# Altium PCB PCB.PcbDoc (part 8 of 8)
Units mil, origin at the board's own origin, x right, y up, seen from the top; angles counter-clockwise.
Board outline 11229.24 x 7764.43 mil, 14 copper layers (Top Layer, GND1, Signal 1, GND2, Signal 2, GND3, Singal 3, Power 1, GND4, Power 2, GND5, Power 3, GND6, Bottom Layer), stack 91.892 mil thick; 877 components, 305 nets, 2660 pads, 2851 vias.
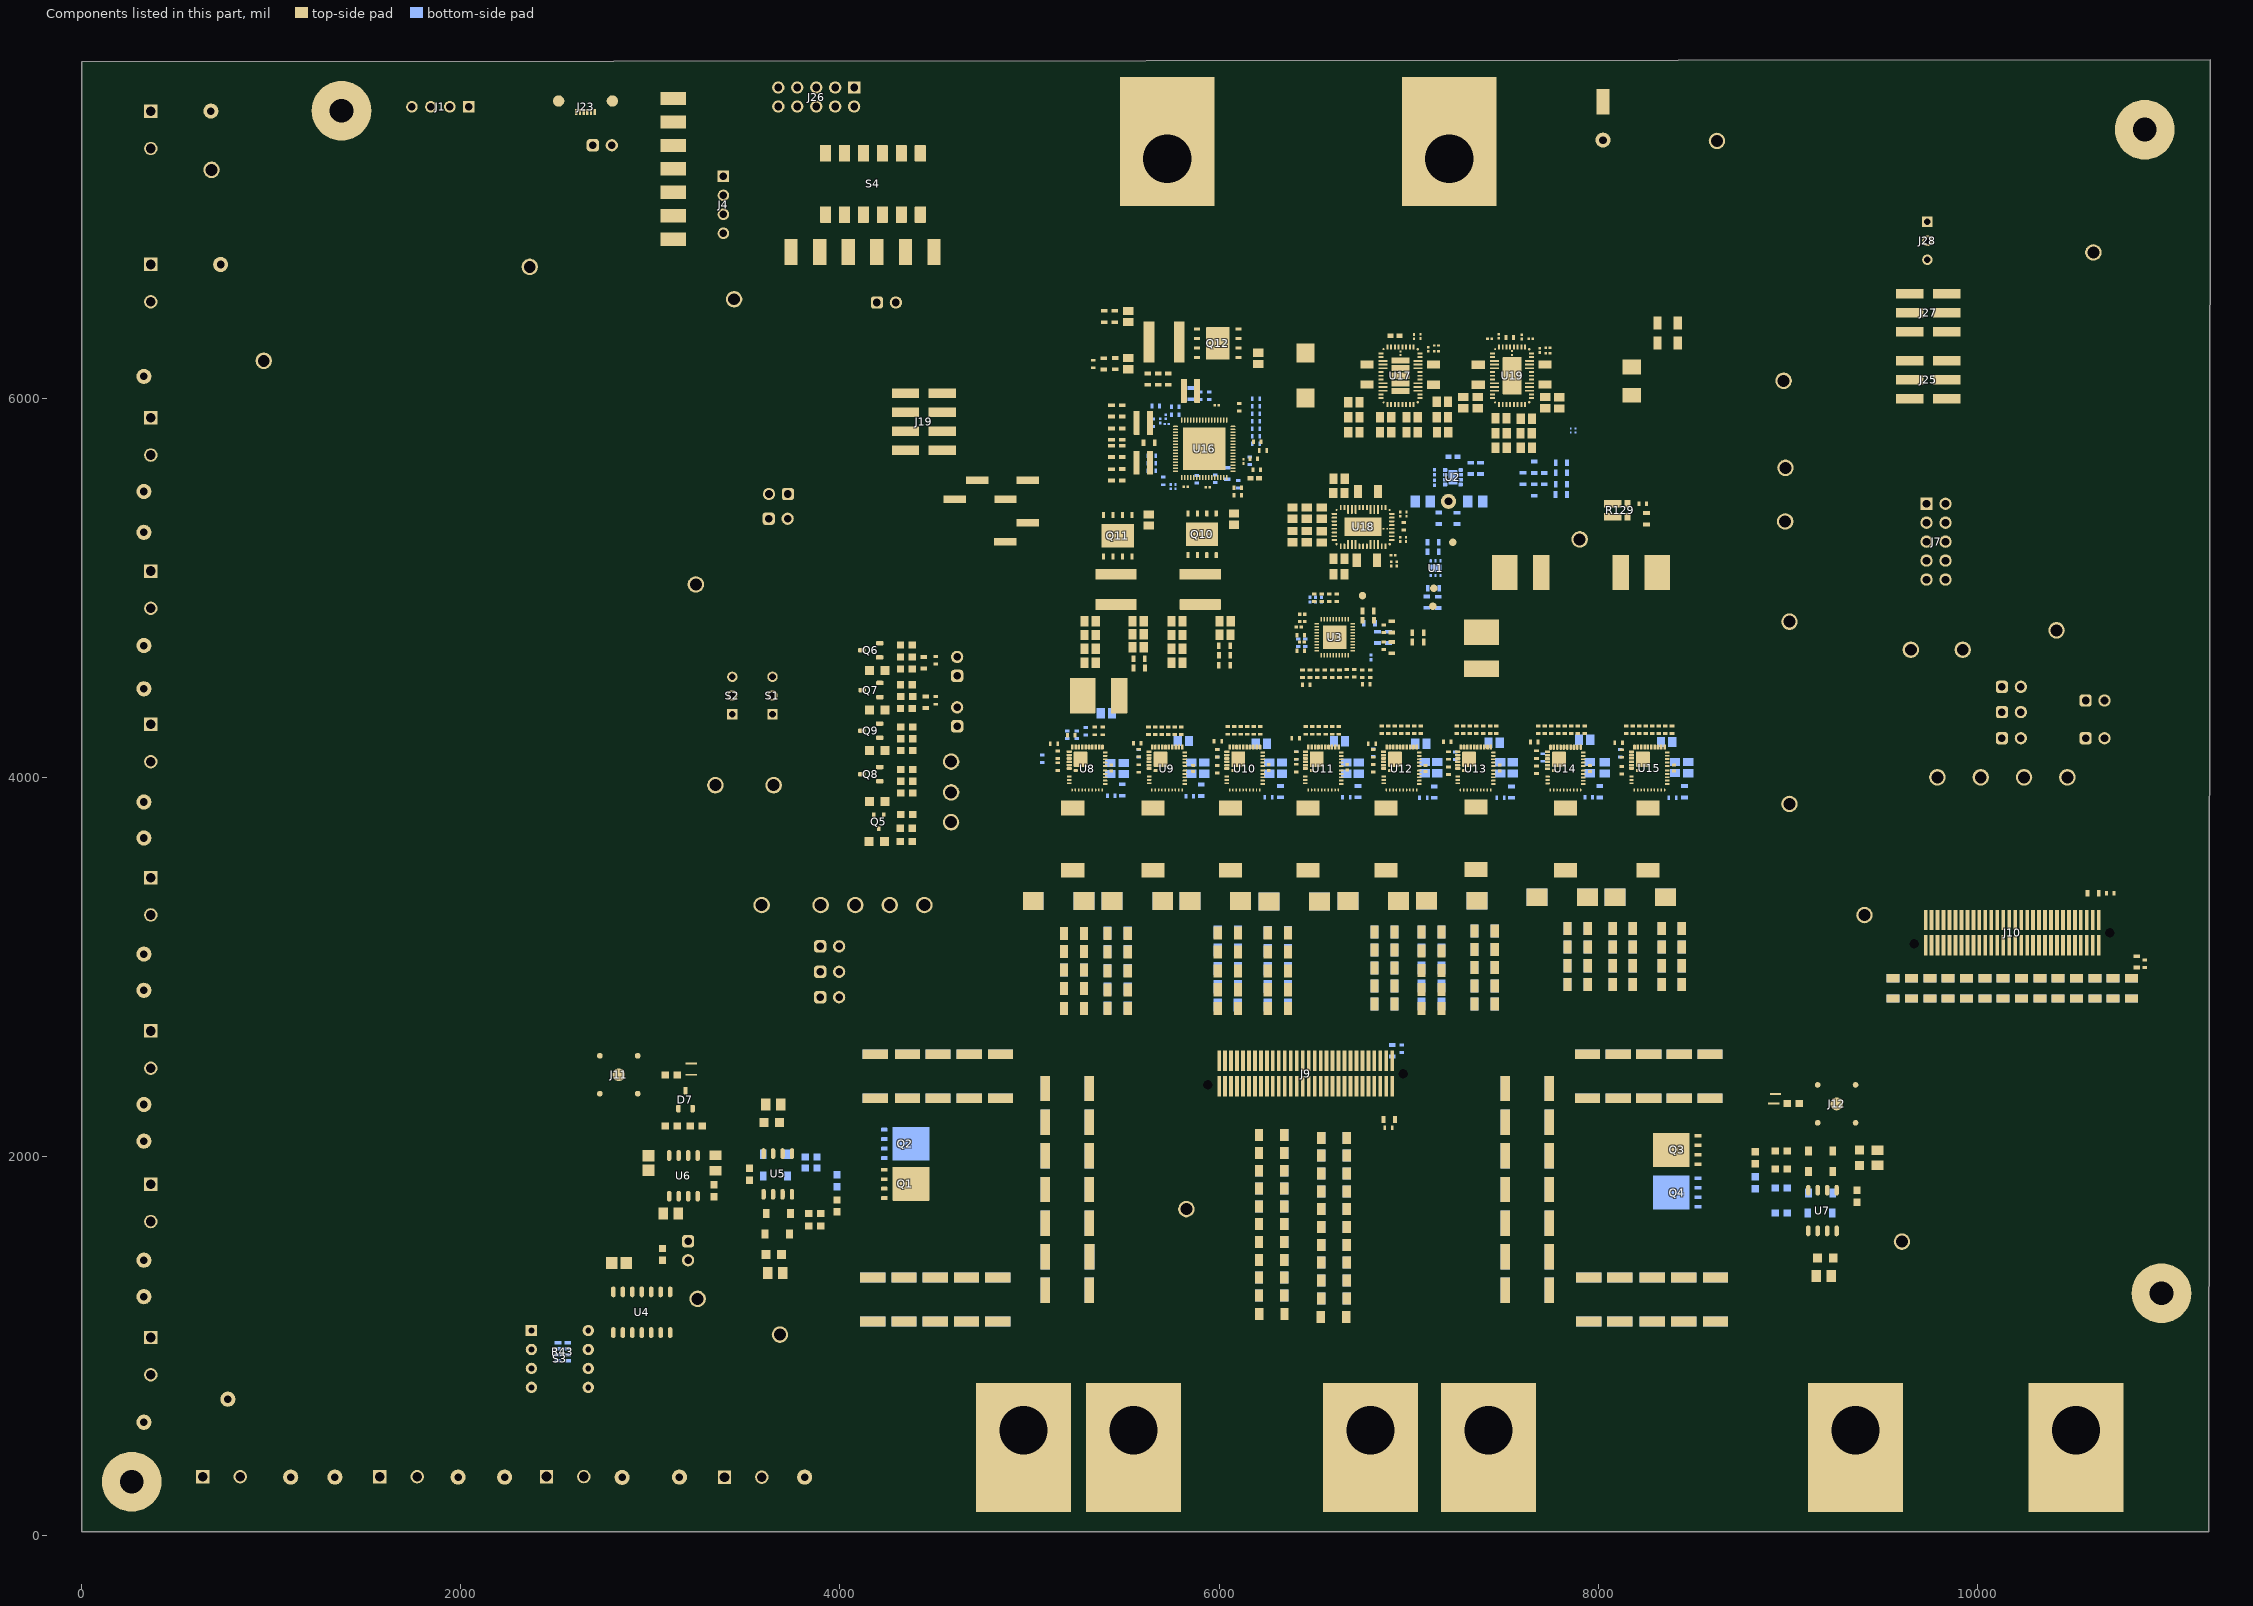
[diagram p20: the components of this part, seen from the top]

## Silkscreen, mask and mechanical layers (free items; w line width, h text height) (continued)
Drill Drawing:
  drawing of 184 lines, arcs and shapes, not listed
  text "Symbol" at -412.44,13047 h61.47
  text "Quantity" at -155.67,13047 h61.47
  text "Finished Hole Size" at 127.95,13047 h61.47
  text "Plated" at 671.78,13047 h61.47
  text "Hole Type" at 893.16,13047 h61.47
  text "Drill Layer Pair" at 1213.65,13047 h61.47
  text "Hole Tolerance" at 1832.27,13047 h61.47
  text "4" at -155.67,12940.82 h51.23
  text "50.00mil (1.270mm)" at 127.95,12940.82 h51.23
  text "NPTH" at 671.78,12940.82 h51.23
  text "Round" at 893.16,12940.82 h51.23
  text "Top Layer - Bottom Layer" at 1213.65,12940.82 h51.23
  text "2" at -155.67,12834.65 h51.23
  text "6.00mil (0.152mm)" at 127.95,12834.65 h51.23
  text "PTH" at 671.78,12834.65 h51.23
  text "Round" at 893.16,12834.65 h51.23
  text "Top Layer - Bottom Layer" at 1213.65,12834.65 h51.23
  text "323" at -155.67,12728.47 h51.23
  text "7.87mil (0.200mm)" at 127.95,12728.47 h51.23
  text "PTH" at 671.78,12728.47 h51.23
  text "Round" at 893.16,12728.47 h51.23
  text "Top Layer - Bottom Layer" at 1213.65,12728.47 h51.23
  text "473" at -155.67,12622.29 h51.23
  text "8.00mil (0.203mm)" at 127.95,12622.29 h51.23
  text "PTH" at 671.78,12622.29 h51.23
  text "Round" at 893.16,12622.29 h51.23
  text "Top Layer - Bottom Layer" at 1213.65,12622.29 h51.23
  text "12" at -155.67,12516.12 h51.23
  text "12.00mil (0.305mm)" at 127.95,12516.12 h51.23
  text "PTH" at 671.78,12516.12 h51.23
  text "Round" at 893.16,12516.12 h51.23
  text "Top Layer - Bottom Layer" at 1213.65,12516.12 h51.23
  text "1577" at -155.67,12409.94 h51.23
  text "15.00mil (0.381mm)" at 127.95,12409.94 h51.23
  text "PTH" at 671.78,12409.94 h51.23
  text "Round" at 893.16,12409.94 h51.23
  text "Top Layer - Bottom Layer" at 1213.65,12409.94 h51.23
  text "464" at -155.67,12303.77 h51.23
  text "16.00mil (0.406mm)" at 127.95,12303.77 h51.23
  text "PTH" at 671.78,12303.77 h51.23
  text "Round" at 893.16,12303.77 h51.23
  text "Top Layer - Bottom Layer" at 1213.65,12303.77 h51.23
  text "8" at -155.67,12197.59 h51.23
  text "31.00mil (0.787mm)" at 127.95,12197.59 h51.23
  text "PTH" at 671.78,12197.59 h51.23
  text "Round" at 893.16,12197.59 h51.23
  text "Top Layer - Bottom Layer" at 1213.65,12197.59 h51.23
  text "9" at -155.67,12091.41 h51.23
  text "35.43mil (0.900mm)" at 127.95,12091.41 h51.23
  text "PTH" at 671.78,12091.41 h51.23
  text "Round" at 893.16,12091.41 h51.23
  text "Top Layer - Bottom Layer" at 1213.65,12091.41 h51.23
  text "76" at -155.67,11985.24 h51.23
  text "40.00mil (1.016mm)" at 127.95,11985.24 h51.23
  text "PTH" at 671.78,11985.24 h51.23
  text "Round" at 893.16,11985.24 h51.23
  text "Top Layer - Bottom Layer" at 1213.65,11985.24 h51.23
  text "8" at -155.67,11879.06 h51.23
  text "40.16mil (1.020mm)" at 127.95,11879.06 h51.23
  text "PTH" at 671.78,11879.06 h51.23
  text "Round" at 893.16,11879.06 h51.23
  text "Top Layer - Bottom Layer" at 1213.65,11879.06 h51.23
  text "26" at -155.67,11772.89 h51.23
  text "51.18mil (1.300mm)" at 127.95,11772.89 h51.23
  text "PTH" at 671.78,11772.89 h51.23
  text "Round" at 893.16,11772.89 h51.23
  text "Top Layer - Bottom Layer" at 1213.65,11772.89 h51.23
  text "35" at -155.67,11666.71 h51.23
  text "63.00mil (1.600mm)" at 127.95,11666.71 h51.23
  text "PTH" at 671.78,11666.71 h51.23
  text "Round" at 893.16,11666.71 h51.23
  text "Top Layer - Bottom Layer" at 1213.65,11666.71 h51.23
  text "4" at -155.67,11560.53 h51.23
  text "125.98mil (3.200mm)" at 127.95,11560.53 h51.23
  text "PTH" at 671.78,11560.53 h51.23
  text "Round" at 893.16,11560.53 h51.23
  text "Top Layer - Bottom Layer" at 1213.65,11560.53 h51.23
  text "8" at -155.67,11454.36 h51.23
  text "254.00mil (6.452mm)" at 127.95,11454.36 h51.23
  text "PTH" at 671.78,11454.36 h51.23
  text "Round" at 893.16,11454.36 h51.23
  text "Top Layer - Bottom Layer" at 1213.65,11454.36 h51.23
  text "3029 Total" at -155.67,11348.18 h51.23
  text ".Layer_Name" at 577,-858.49 h60
M17 Embedded Cavity:
  text ".Layer_Name" at 577,-858.49 h60
M18 Embedded Assembly:
  text ".Layer_Name" at 577,-858.49 h60
M19 Embedded Keepout:
  text ".Layer_Name" at 577,-858.49 h60

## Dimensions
8472.5,6494.6 to 8491.48,2724.26 on Top Overlay
4962.6,6494.6 to 8479.19,2839.73 on Top Overlay
0,21 to 11220.55,21 on M2 Board Dimensions
0,-400 to 1000,-400 on M2 Board Dimensions
0,21 to 0,7775.19 on M2 Board Dimensions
